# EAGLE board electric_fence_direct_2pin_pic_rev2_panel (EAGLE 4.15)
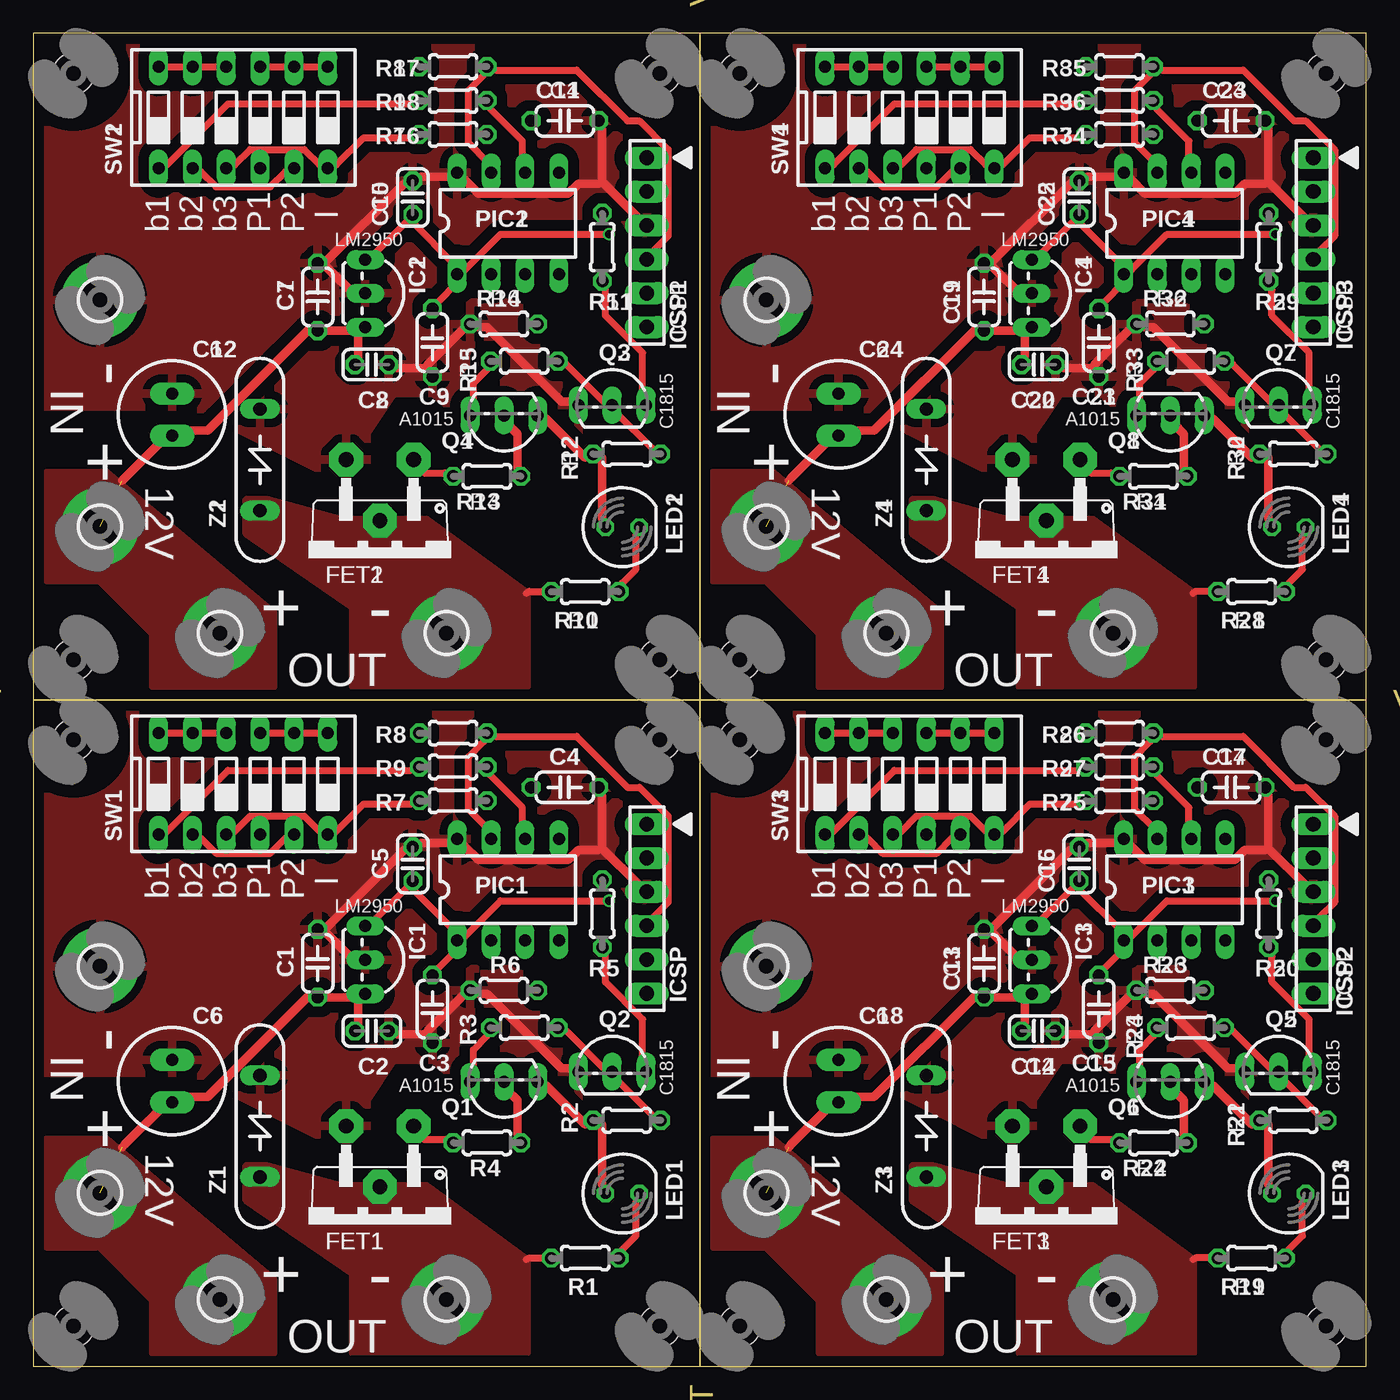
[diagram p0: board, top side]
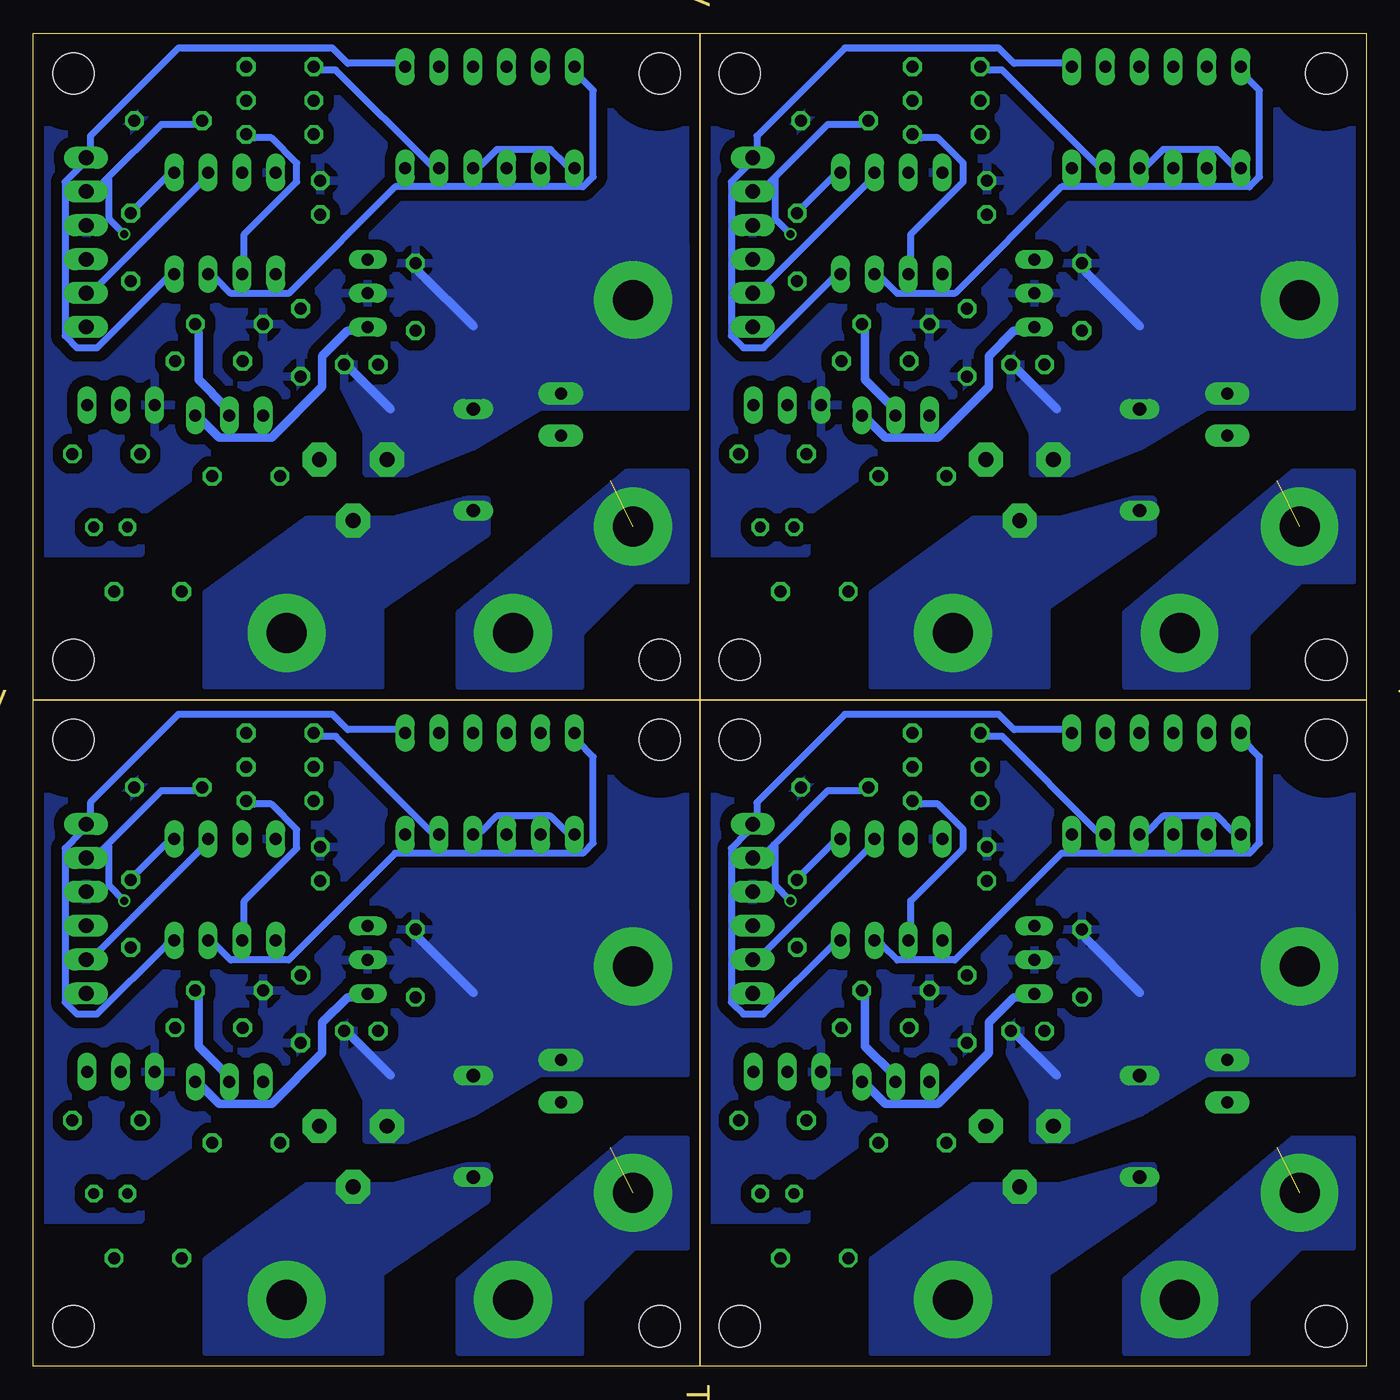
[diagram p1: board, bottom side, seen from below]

Size 100 x 100 mm. Coordinates in mm from the lower left corner, seen from the top.
Outline: 50,0 0,0 0,50
Outline: 50,0 50,50
Outline: 50,50 0,50
Outline: 0,50 50,50
Outline: 50,50 50,100
Outline: 50,100 0,100 0,50
Outline: 50,0 100,0 100,50
Outline: 100,50 50,50
Outline: 50,50 50,0
Outline: 50,50 100,50
Outline: 100,50 100,100 50,100
Outline: 50,100 50,50
Copper layers (1*16): Top 0.035mm / dielectric 1.5mm / Bottom 0.035mm
Design rules "FUSION_IIZUKA_STANDARD": minimum track width 6mil, minimum drill 0.6mm, track to track 8mil, track to pad 8mil, pad to pad 8mil, via to via 8mil, smd to smd 0mil, copper to edge 30mil, drill to drill 10mil, minimum pad ring 10mil, minimum via ring 6mil, stop-mask expansion 2mil, vias tented up to drill 100mil, thermal gap 24mil
Net classes: 0 default: width 0.508 mm, drill 0.406 mm; 1 power: width 0.635 mm, drill 0.508 mm

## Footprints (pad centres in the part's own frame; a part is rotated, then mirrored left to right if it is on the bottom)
C050-024X044_OLMX = drill 0.9 octagon: 1 -2.54,0; 2 2.54,0
C025-024X044_OLMX = drill 0.9 octagon: 1 -1.27,0; 2 1.27,0
C = drill 0.9 pad 1.676 long: P$1 1.27,0; P$2 -1.905,0
TO-220HV = drill 1.118 pad 2.54 octagon: 1 -2.54,-1.016; 2 0,3.556; 3 2.54,-1.016
3,0-PAD-NOLING = drill 3 pad 5.842 round: B3,0 0,0
3.1-HOLL = hole 3.1: 0,0
TO-92INLINE = drill 0.9 long: 1 -2.54,0; 2 0,0; 3 2.54,0
PIC_ICSP = drill 1.1 long: MCLR -6.35,0; NC 6.35,0; PGC 3.81,0; PGD 1.27,0; VDD -3.81,0; VSS -1.27,0
LED5MM_OLMX = drill 0.8 octagon: A -1.27,0; K 1.27,0
DIL8_OLMX = drill 0.9 long: 1 -3.81,-3.81; 2 -1.27,-3.81; 3 1.27,-3.81; 4 3.81,-3.81; 5 3.81,3.81; 6 1.27,3.81; 7 -1.27,3.81; 8 -3.81,3.81
TO92-BCE_OLMX = drill 0.9 long: B 2.54,0; C 0,0; E -2.54,0
0204/5_OLMX = drill 0.9 octagon: 1 -2.54,0; 2 2.54,0
DS-06_OLMX = drill 0.9 long: 1 -6.35,-3.81; 2 -3.81,-3.81; 3 -1.27,-3.81; 4 1.27,-3.81; 5 3.81,-3.81; 6 6.35,-3.81; 7 6.35,3.81; 8 3.81,3.81; 9 1.27,3.81; 10 -1.27,3.81; 11 -3.81,3.81; 12 -6.35,3.81
ZNR14MM = drill 1 long: P$1 -3.81,0; P$2 3.81,0

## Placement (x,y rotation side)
C1  10uF  [C050-024X044_OLMX]  21.34,30.23 270 top
C2  0.1uF  [C025-024X044_OLMX]  25.4,25.15 180 top
C3  10uF  [C050-024X044_OLMX]  29.94,26.8 90 top
C4  10uF  [C050-024X044_OLMX]  39.88,43.43 180 top
C5  0.1uF  [C025-024X044_OLMX]  28.47,37.68 270 top
C6  35V 220uF  [C]  10.41,21.08 270 top
C7  10uF  [C050-024X044_OLMX]  21.34,80.23 270 top
C8  0.1uF  [C025-024X044_OLMX]  25.4,75.15 180 top
C9  10uF  [C050-024X044_OLMX]  29.94,76.8 90 top
C10  0.1uF  [C025-024X044_OLMX]  28.47,87.68 270 top
C11  10uF  [C050-024X044_OLMX]  39.88,93.43 180 top
C12  35V 220uF  [C]  10.41,71.08 270 top
C13  10uF  [C050-024X044_OLMX]  71.34,30.23 270 top
C14  0.1uF  [C025-024X044_OLMX]  75.4,25.15 180 top
C15  10uF  [C050-024X044_OLMX]  79.94,26.8 90 top
C16  0.1uF  [C025-024X044_OLMX]  78.47,37.68 270 top
C17  10uF  [C050-024X044_OLMX]  89.88,43.43 180 top
C18  35V 220uF  [C]  60.41,21.08 270 top
C19  10uF  [C050-024X044_OLMX]  71.34,80.23 270 top
C20  0.1uF  [C025-024X044_OLMX]  75.4,75.15 180 top
C21  10uF  [C050-024X044_OLMX]  79.94,76.8 90 top
C22  0.1uF  [C025-024X044_OLMX]  78.47,87.68 270 top
C23  10uF  [C050-024X044_OLMX]  89.88,93.43 180 top
C24  35V 220uF  [C]  60.41,71.08 270 top
FET1  FQPF12N60C  [TO-220HV]  26,17 180 top
FET2  FQPF12N60C  [TO-220HV]  26,67 180 top
FET3  FQPF12N60C  [TO-220HV]  76,17 180 top
FET4  FQPF12N60C  [TO-220HV]  76,67 180 top
H1  [3,0-PAD-NOLING]  5,13 0 top
H2  [3,0-PAD-NOLING]  14,5 0 top
H3  [3,0-PAD-NOLING]  31,5 0 top
H4  [3,0-PAD-NOLING]  5,30 0 top
H5  MOUNT-HOLE3.1  [3.1-HOLL]  3,47 0 top
H6  MOUNT-HOLE3.1  [3.1-HOLL]  47,47 0 top
H7  MOUNT-HOLE3.1  [3.1-HOLL]  3,3 0 top
H8  MOUNT-HOLE3.1  [3.1-HOLL]  47,3 0 top
H9  [3,0-PAD-NOLING]  5,63 0 top
H10  [3,0-PAD-NOLING]  31,55 0 top
H11  [3,0-PAD-NOLING]  14,55 0 top
H12  [3,0-PAD-NOLING]  5,80 0 top
H13  MOUNT-HOLE3.1  [3.1-HOLL]  3,97 0 top
H14  MOUNT-HOLE3.1  [3.1-HOLL]  47,97 0 top
H15  MOUNT-HOLE3.1  [3.1-HOLL]  3,53 0 top
H16  MOUNT-HOLE3.1  [3.1-HOLL]  47,53 0 top
H17  [3,0-PAD-NOLING]  55,13 0 top
H18  [3,0-PAD-NOLING]  81,5 0 top
H19  [3,0-PAD-NOLING]  64,5 0 top
H20  [3,0-PAD-NOLING]  55,30 0 top
H21  MOUNT-HOLE3.1  [3.1-HOLL]  53,47 0 top
H22  MOUNT-HOLE3.1  [3.1-HOLL]  97,47 0 top
H23  MOUNT-HOLE3.1  [3.1-HOLL]  53,3 0 top
H24  MOUNT-HOLE3.1  [3.1-HOLL]  97,3 0 top
H25  [3,0-PAD-NOLING]  55,63 0 top
H26  [3,0-PAD-NOLING]  81,55 0 top
H27  [3,0-PAD-NOLING]  64,55 0 top
H28  [3,0-PAD-NOLING]  55,80 0 top
H29  MOUNT-HOLE3.1  [3.1-HOLL]  53,97 0 top
H30  MOUNT-HOLE3.1  [3.1-HOLL]  97,97 0 top
H31  MOUNT-HOLE3.1  [3.1-HOLL]  53,53 0 top
H32  MOUNT-HOLE3.1  [3.1-HOLL]  97,53 0 top
IC1  LM2950G-5.0  [TO-92INLINE]  24.91,30.49 270 top
IC2  LM2950G-5.0  [TO-92INLINE]  24.91,80.49 270 top
IC3  LM2950G-5.0  [TO-92INLINE]  74.91,30.49 270 top
IC4  LM2950G-5.0  [TO-92INLINE]  74.91,80.49 270 top
ICSP  PIC_ICSP  [PIC_ICSP]  46.03,34.32 270 top
ICSP1  PIC_ICSP  [PIC_ICSP]  46.03,84.32 270 top
ICSP2  PIC_ICSP  [PIC_ICSP]  96.03,34.32 270 top
ICSP3  PIC_ICSP  [PIC_ICSP]  96.03,84.32 270 top
LED1  [LED5MM_OLMX]  44.2,12.95 0 top
LED2  [LED5MM_OLMX]  44.2,62.95 0 top
LED3  [LED5MM_OLMX]  94.2,12.95 0 top
LED4  [LED5MM_OLMX]  94.2,62.95 0 top
PIC1  PIC12F1822  [DIL8_OLMX]  35.62,35.75 0 top
PIC2  PIC12F1822  [DIL8_OLMX]  35.62,85.75 0 top
PIC3  PIC12F1822  [DIL8_OLMX]  85.62,35.75 0 top
PIC4  PIC12F1822  [DIL8_OLMX]  85.62,85.75 0 top
Q1  2SA1015  [TO92-BCE_OLMX]  35.31,21.34 180 top
Q2  2SC1815-Y  [TO92-BCE_OLMX]  43.43,22.1 0 top
Q3  2SC1815-Y  [TO92-BCE_OLMX]  43.43,72.1 0 top
Q4  2SA1015  [TO92-BCE_OLMX]  35.31,71.34 180 top
Q5  2SC1815-Y  [TO92-BCE_OLMX]  93.43,22.1 0 top
Q6  2SA1015  [TO92-BCE_OLMX]  85.31,21.34 180 top
Q7  2SC1815-Y  [TO92-BCE_OLMX]  93.43,72.1 0 top
Q8  2SA1015  [TO92-BCE_OLMX]  85.31,71.34 180 top
R1  10k  [0204/5_OLMX]  41.4,8.11 180 top
R2  10k  [0204/5_OLMX]  44.53,18.45 180 top
R3  10k  [0204/5_OLMX]  36.83,25.4 180 top
R4  100  [0204/5_OLMX]  34.04,16.76 180 top
R5  10k  [0204/5_OLMX]  42.69,33.96 270 top
R6  1k  [0204/5_OLMX]  35.31,28.19 0 top
R7  1k  [0204/5_OLMX]  31.5,42.42 0 top
R8  1k  [0204/5_OLMX]  31.5,47.5 0 top
R9  1k  [0204/5_OLMX]  31.5,44.96 0 top
R10  10k  [0204/5_OLMX]  41.4,58.11 180 top
R11  10k  [0204/5_OLMX]  42.69,83.96 270 top
R12  10k  [0204/5_OLMX]  44.53,68.45 180 top
R13  100  [0204/5_OLMX]  34.04,66.76 180 top
R14  1k  [0204/5_OLMX]  35.31,78.19 0 top
R15  10k  [0204/5_OLMX]  36.83,75.4 180 top
R16  1k  [0204/5_OLMX]  31.5,92.42 0 top
R17  1k  [0204/5_OLMX]  31.5,97.5 0 top
R18  1k  [0204/5_OLMX]  31.5,94.96 0 top
R19  10k  [0204/5_OLMX]  91.4,8.11 180 top
R20  10k  [0204/5_OLMX]  92.69,33.96 270 top
R21  10k  [0204/5_OLMX]  94.53,18.45 180 top
R22  100  [0204/5_OLMX]  84.04,16.76 180 top
R23  1k  [0204/5_OLMX]  85.31,28.19 0 top
R24  10k  [0204/5_OLMX]  86.83,25.4 180 top
R25  1k  [0204/5_OLMX]  81.5,42.42 0 top
R26  1k  [0204/5_OLMX]  81.5,47.5 0 top
R27  1k  [0204/5_OLMX]  81.5,44.96 0 top
R28  10k  [0204/5_OLMX]  91.4,58.11 180 top
R29  10k  [0204/5_OLMX]  92.69,83.96 270 top
R30  10k  [0204/5_OLMX]  94.53,68.45 180 top
R31  100  [0204/5_OLMX]  84.04,66.76 180 top
R32  1k  [0204/5_OLMX]  85.31,78.19 0 top
R33  10k  [0204/5_OLMX]  86.83,75.4 180 top
R34  1k  [0204/5_OLMX]  81.5,92.42 0 top
R35  1k  [0204/5_OLMX]  81.5,97.5 0 top
R36  1k  [0204/5_OLMX]  81.5,94.96 0 top
SW1  [DS-06_OLMX]  15.75,43.69 0 top
SW2  [DS-06_OLMX]  15.75,93.69 0 top
SW3  [DS-06_OLMX]  65.75,43.69 0 top
SW4  [DS-06_OLMX]  65.75,93.69 0 top
Z1  14D471K  [ZNR14MM]  17,18 90 top
Z2  14D471K  [ZNR14MM]  17,68 90 top
Z3  14D471K  [ZNR14MM]  67,18 90 top
Z4  14D471K  [ZNR14MM]  67,68 90 top

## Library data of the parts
C1-C5 C7-C11 C13-C17 C19-C23 R1-R36 = rcl
C6 C12 C18 C24 = 002mylib
FET1-FET4 = transistor-power
H1-H32 = holes
IC1-IC4 = linear
ICSP ICSP1-ICSP3 Z1-Z4 = 001mylib
LED1-LED4 = led
PIC1-PIC4 = microchip
Q1-Q8 = transistor
SW1-SW4 = switch-dil

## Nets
+5V: C3.2 C4.2 C5.2 IC1.1 ICSP.VDD PIC1.1
+5V1: C9.2 C10.2 C11.2 IC2.1 ICSP1.VDD PIC2.1
+5V2: C15.2 C16.2 C17.2 IC3.1 ICSP2.VDD PIC3.1
+5V3: C21.2 C22.2 C23.2 IC4.1 ICSP3.VDD PIC4.1
GND [power]: C1.1 C2.1 C3.1 C4.1 C5.1 C6.P$2 FET1.3 H4.B3,0 IC1.2 ICSP.VSS PIC1.8 Q2.E R6.1 Z1.P$2
GND1 [power]: C7.1 C8.1 C9.1 C10.1 C11.1 C12.P$2 FET2.3 H12.B3,0 IC2.2 ICSP1.VSS PIC2.8 Q3.E R14.1 Z2.P$2
GND2 [power]: C13.1 C14.1 C15.1 C16.1 C17.1 C18.P$2 FET3.3 H20.B3,0 IC3.2 ICSP2.VSS PIC3.8 Q5.E R23.1 Z3.P$2
GND3 [power]: C19.1 C20.1 C21.1 C22.1 C23.1 C24.P$2 FET4.3 H28.B3,0 IC4.2 ICSP3.VSS PIC4.8 Q7.E R32.1 Z4.P$2
N$1: PIC1.2 R7.2
N$2: Q2.B R5.2
N$3: FET1.1 R4.2
N$4: R8.1 SW1.2 SW1.5
N$5: LED2.K R10.1
N$6 [power]: Q1.C R4.1 R6.2
N$7: LED1.K R1.1
N$8: Q1.B R3.2
N$9: ICSP.MCLR PIC1.4 SW1.7 SW1.8 SW1.9
N$10: R9.1 SW1.1 SW1.4
N$11: R7.1 SW1.3 SW1.6
N$12: Q2.C R2.1 R3.1
N$13: ICSP.PGD PIC1.7 R8.2
N$14: PIC1.3 SW1.10 SW1.11 SW1.12
N$15: PIC1.5 R5.1
N$16: ICSP.PGC PIC1.6 R9.2
N$17: PIC2.5 R11.1
N$18: Q3.B R11.2
N$19: FET2.1 R13.2
N$20: ICSP1.MCLR PIC2.4 SW2.7 SW2.8 SW2.9
N$21: R18.1 SW2.1 SW2.4
N$22: R17.1 SW2.2 SW2.5
N$23: R16.1 SW2.3 SW2.6
N$24: Q3.C R12.1 R15.1
N$25 [power]: Q4.C R13.1 R14.2
N$26: Q4.B R15.2
N$27: PIC2.3 SW2.10 SW2.11 SW2.12
N$28: PIC2.2 R16.2
N$29: ICSP1.PGD PIC2.7 R17.2
N$30: ICSP1.PGC PIC2.6 R18.2
N$31: LED3.K R19.1
N$32: PIC3.5 R20.1
N$33: Q5.B R20.2
N$34: FET3.1 R22.2
N$35: ICSP2.MCLR PIC3.4 SW3.7 SW3.8 SW3.9
N$36: R27.1 SW3.1 SW3.4
N$37: R26.1 SW3.2 SW3.5
N$38: R25.1 SW3.3 SW3.6
N$39: Q5.C R21.1 R24.1
N$40 [power]: Q6.C R22.1 R23.2
N$41: Q6.B R24.2
N$42: PIC3.3 SW3.10 SW3.11 SW3.12
N$43: PIC3.2 R25.2
N$44: ICSP2.PGD PIC3.7 R26.2
N$45: ICSP2.PGC PIC3.6 R27.2
N$46: LED4.K R28.1
N$47: PIC4.5 R29.1
N$48: Q7.B R29.2
N$49: FET4.1 R31.2
N$50: ICSP3.MCLR PIC4.4 SW4.7 SW4.8 SW4.9
N$51: R36.1 SW4.1 SW4.4
N$52: R35.1 SW4.2 SW4.5
N$53: R34.1 SW4.3 SW4.6
N$54: Q7.C R30.1 R33.1
N$55 [power]: Q8.C R31.1 R32.2
N$56: Q8.B R33.2
N$57: PIC4.3 SW4.10 SW4.11 SW4.12
N$58: PIC4.2 R34.2
N$59: ICSP3.PGD PIC4.7 R35.2
N$60: ICSP3.PGC PIC4.6 R36.2
OUT-: FET1.2 H3.B3,0 R1.2 Z1.P$1
OUT-1: FET2.2 H10.B3,0 R10.2 Z2.P$1
OUT-2: FET3.2 H18.B3,0 R19.2 Z3.P$1
OUT-3: FET4.2 H26.B3,0 R28.2 Z4.P$1
VPP [power]: C1.2 C2.2 C6.P$1 H1.B3,0 H2.B3,0 IC1.3 LED1.A Q1.E R2.2
VPP1 [power]: C7.2 C8.2 C12.P$1 H9.B3,0 H11.B3,0 IC2.3 LED2.A Q4.E R12.2
VPP2 [power]: C13.2 C14.2 C18.P$1 H17.B3,0 H19.B3,0 IC3.3 LED3.A Q6.E R21.2
VPP3 [power]: C19.2 C20.2 C24.P$1 H25.B3,0 H27.B3,0 IC4.3 LED4.A Q8.E R30.2

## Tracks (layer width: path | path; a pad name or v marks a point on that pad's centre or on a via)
+5V  (via drill 0.6)
  Top 0.508: C3.2 30.35,29.84 31.75,31.24 PIC1.1 | IC1.1 25.53,33.4 28.07,35.94 C5.2 28.45,35.81 31.62,32.64 PIC1.1 | v43.18,34.92 35.05,34.92 32.38,32.26 PIC1.1
  Bottom 0.508: 44.45,39.12 45.21,38.35 ICSP.VDD | 44.45,39.12 40.39,43.18 37.97,43.18 C4.2 | v43.18,34.92 44.32,36.07 44.32,38.99 44.45,39.12
+5V1  (via drill 0.6)
  Top 0.508: C9.2 30.35,79.84 31.75,81.24 PIC2.1 | IC2.1 25.53,83.4 28.07,85.94 C10.2 28.45,85.81 31.62,82.64 PIC2.1 | v43.18,84.92 35.05,84.92 32.38,82.26 PIC2.1
  Bottom 0.508: 44.45,89.12 45.21,88.35 ICSP1.VDD | 44.45,89.12 40.39,93.18 37.97,93.18 C11.2 | v43.18,84.92 44.32,86.07 44.32,88.99 44.45,89.12
+5V2  (via drill 0.6)
  Top 0.508: C15.2 80.35,29.84 81.75,31.24 PIC3.1 | IC3.1 75.53,33.4 78.07,35.94 C16.2 78.45,35.81 81.62,32.64 PIC3.1 | v93.18,34.92 85.05,34.92 82.39,32.26 PIC3.1
  Bottom 0.508: 94.45,39.12 95.21,38.35 ICSP2.VDD | 94.45,39.12 90.39,43.18 87.97,43.18 C17.2 | v93.18,34.92 94.32,36.07 94.32,38.99 94.45,39.12
+5V3  (via drill 0.6)
  Top 0.508: C21.2 80.35,79.84 81.75,81.24 PIC4.1 | IC4.1 75.53,83.4 78.07,85.94 C22.2 78.45,85.81 81.62,82.64 PIC4.1 | v93.18,84.92 85.05,84.92 82.39,82.26 PIC4.1
  Bottom 0.508: 94.45,89.12 95.21,88.35 ICSP3.VDD | 94.45,89.12 90.39,93.18 87.97,93.18 C23.2 | v93.18,84.92 94.32,86.07 94.32,88.99 94.45,89.12
GND
  Top 0.635: 29.59,24.89 27.3,24.89 C2.1 | 29.59,24.89 C3.1 | 29.59,24.89 29.59,25.15 32.26,27.81 R6.1 33.4,27.94 34.04,27.94 39.62,22.35 40.26,22.35 Q2.E | 42.67,38.86 42.67,42.8 C4.1 | 42.67,38.86 45.47,36.07 ICSP.VSS | IC1.2 24.26,30.23 21.97,32.51 C1.1 21.97,32.89 27.81,38.73 C5.1 29.08,39.24 31.24,39.24 PIC1.8 32.26,39.12 33.4,37.97 40.13,37.97 40.89,38.73 42.42,38.73 42.67,38.86
  Bottom 0.635: C2.1 26.16,24.77 23.2,21.8 | 16.98,28.02 21.08,32.13 C1.1
  pour Bottom (isolate 0.61, no thermals): 1,34.03 11,34 25,20 25,17 22,17 17,19 12,22 1,22
  pour Bottom (isolate 0.813, rank 2): 0,50 50,50 50,11 42,11 42,14 28,24 27,24 25,20 11,34 0,34
  pour Top (isolate 0.813, rank 2): 0,50 50,50 50,11 42,11 42,13 30,23 27,23 25,20 25,17 22,17 12,22 0,22
GND1
  Top 0.635: 29.59,74.89 27.3,74.89 C8.1 | 29.59,74.89 C9.1 | 29.59,74.89 29.59,75.15 32.26,77.81 R14.1 33.4,77.94 34.04,77.94 39.62,72.35 40.26,72.35 Q3.E | 42.67,88.86 42.67,92.8 C11.1 | 42.67,88.86 45.47,86.07 ICSP1.VSS | IC2.2 24.26,80.23 21.97,82.51 C7.1 21.97,82.89 27.81,88.73 C10.1 29.08,89.24 31.24,89.24 PIC2.8 32.26,89.12 33.4,87.97 40.13,87.97 40.89,88.73 42.42,88.73 42.67,88.86
  Bottom 0.635: C8.1 26.16,74.77 23.2,71.8 | 16.98,78.03 21.08,82.13 C7.1
  pour Bottom (isolate 0.61, no thermals): 1,84.03 11,84 25,70 25,67 22,67 17,69 12,72 1,72
  pour Bottom (isolate 0.813, rank 2): 0,100 50,100 50,61 42,61 42,64 28,74 27,74 25,70 11,84 0,84
  pour Top (isolate 0.813, rank 2): 0,100 50,100 50,61 42,61 42,63 30,73 27,73 25,70 25,67 22,67 12,72 0,72
GND2
  Top 0.635: 79.59,24.89 77.31,24.89 C14.1 | 79.59,24.89 C15.1 | 79.59,24.89 79.59,25.15 82.26,27.81 R23.1 83.4,27.94 84.04,27.94 89.62,22.35 90.26,22.35 Q5.E | 92.67,38.86 92.67,42.8 C17.1 | 92.67,38.86 95.47,36.07 ICSP2.VSS | IC3.2 74.26,30.23 71.97,32.51 C13.1 71.97,32.89 77.81,38.73 C16.1 79.08,39.24 81.24,39.24 PIC3.8 82.26,39.12 83.4,37.97 90.13,37.97 90.89,38.73 92.42,38.73 92.67,38.86
  Bottom 0.635: C14.1 76.16,24.77 73.2,21.8 | 66.97,28.02 71.08,32.13 C13.1
  pour Bottom (isolate 0.61, no thermals): 51,34.03 61,34 75,20 75,17 72,17 67,19 62,22 51,22
  pour Bottom (isolate 0.813, rank 2): 50,50 100,50 100,11 92,11 92,14 78,24 77,24 75,20 61,34 50,34
  pour Top (isolate 0.813, rank 2): 50,50 100,50 100,11 92,11 92,13 80,23 77,23 75,20 75,17 72,17 62,22 50,22
GND3
  Top 0.635: 79.59,74.89 77.31,74.89 C20.1 | 79.59,74.89 C21.1 | 79.59,74.89 79.59,75.15 82.26,77.81 R32.1 83.4,77.94 84.04,77.94 89.62,72.35 90.26,72.35 Q7.E | 92.67,88.86 92.67,92.8 C23.1 | 92.67,88.86 95.47,86.07 ICSP3.VSS | IC4.2 74.26,80.23 71.97,82.51 C19.1 71.97,82.89 77.81,88.73 C22.1 79.08,89.24 81.24,89.24 PIC4.8 82.26,89.12 83.4,87.97 90.13,87.97 90.89,88.73 92.42,88.73 92.67,88.86
  Bottom 0.635: C20.1 76.16,74.77 73.2,71.8 | 66.97,78.03 71.08,82.13 C19.1
  pour Bottom (isolate 0.61, no thermals): 51,84.03 61,84 75,70 75,67 72,67 67,69 62,72 51,72
  pour Bottom (isolate 0.813, rank 2): 50,100 100,100 100,61 92,61 92,64 78,74 77,74 75,70 61,84 50,84
  pour Top (isolate 0.813, rank 2): 50,100 100,100 100,61 92,61 92,63 80,73 77,73 75,70 75,67 72,67 62,72 50,72
N$1
  Bottom 0.508: PIC1.2 34.16,32.64 34.16,34.92 30.23,38.86 30.23,40.26 32.13,42.16 33.4,42.16 R7.2
N$2
  Top 0.508: Q2.B 45.72,22.73 45.72,26.04 42.93,28.83 42.93,30.73 R5.2
N$3
  Top 0.508: R4.2 30.86,17.02 29.34,17.02 FET1.1
N$4
  Top 0.508: SW1.2 12.57,39.62 13.72,38.48 17.78,38.48 18.92,39.62 SW1.5
  Bottom 0.508: R8.1 28.32,47.24 27.3,47.24 20.19,40.13 SW1.5
N$5
  Top 0.508: LED2.K 45.21,62.32 45.21,59.78 44.2,58.76 R10.1
N$6
  Top 0.635: R4.1 36.32,17.4 36.32,19.94 35.56,20.7 Q1.C
  Bottom 0.635: R6.2 37.59,27.56 37.59,24 35.56,21.97 Q1.C
N$7
  Top 0.508: LED1.K 45.21,12.32 45.21,9.78 44.2,8.76 R1.1
N$8
  Top 0.508: Q1.B 33.02,21.97 33.02,23.75 34.04,24.77 R3.2
N$9
  Top 0.508: SW1.9 SW1.8 SW1.7
  Bottom 0.508: PIC1.4 40.01,31.62 45.21,26.42 46.74,26.42 47.62,27.3 47.62,38.86 46.48,40.01 ICSP.MCLR 45.72,41.4 45.72,42.29 39.12,48.9 27.56,48.9 26.42,47.75 22.73,47.75 SW1.7
N$10
  Top 0.508: R9.1 28.32,44.7 14.61,44.7 10.03,40.13 SW1.1
  Bottom 0.508: SW1.1 10.03,40.13 11.18,41.27 15.24,41.27 16.38,40.13 SW1.4
N$11
  Top 0.508: SW1.3 15.11,40.13 16.26,41.27 20.32,41.27 21.46,40.13 SW1.6 22.73,40.13 24.77,42.16 28.32,42.16 R7.1
N$12
  Top 0.508: R3.1 40.01,25.15 42.8,22.35 Q2.C 43.69,21.59 46.48,18.8 R2.1
N$13
  Top 0.508: PIC1.7 34.16,40.26 32.64,41.78 32.64,45.72 33.78,46.86 R8.2 34.67,47.24 40.77,47.24 44.58,43.43 45.47,43.43 47.62,41.27 47.62,34.8 46.48,33.66 ICSP.PGD
N$14
  Top 0.508: SW1.12 SW1.11 SW1.10
  Bottom 0.508: PIC1.3 36.32,31.62 35.18,30.48 30.86,30.48 22.86,38.48 8.76,38.48 8,39.24 8,45.72 9.14,46.86 SW1.12
N$15
  Bottom 0.508: PIC1.5 40.01,39.24 42.29,36.96 R5.1
N$16
  Top 0.508: PIC1.6 36.7,40.26 36.7,41.91 34.29,44.32 R9.2
  Bottom 0.508: ICSP.PGC 45.34,30.86 37.21,38.99 PIC1.6
N$17
  Bottom 0.508: PIC2.5 40.01,89.24 42.29,86.96 R11.1
N$18
  Top 0.508: Q3.B 45.72,72.73 45.72,76.03 42.93,78.83 42.93,80.73 R11.2
N$19
  Top 0.508: R13.2 30.86,67.02 29.34,67.02 FET2.1
N$20
  Top 0.508: SW2.9 SW2.8 SW2.7
  Bottom 0.508: PIC2.4 40.01,81.62 45.21,76.42 46.74,76.42 47.62,77.31 47.62,88.86 46.48,90 ICSP1.MCLR 45.72,91.4 45.72,92.29 39.12,98.89 27.56,98.89 26.42,97.75 22.73,97.75 SW2.7
N$21
  Top 0.508: R18.1 28.32,94.7 14.61,94.7 10.03,90.13 SW2.1
  Bottom 0.508: SW2.1 10.03,90.13 11.18,91.28 15.24,91.28 16.38,90.13 SW2.4
N$22
  Top 0.508: SW2.2 12.57,89.62 13.72,88.48 17.78,88.48 18.92,89.62 SW2.5
  Bottom 0.508: R17.1 28.32,97.24 27.3,97.24 20.19,90.13 SW2.5
N$23
  Top 0.508: SW2.3 15.11,90.13 16.26,91.28 20.32,91.28 21.46,90.13 SW2.6 22.73,90.13 24.77,92.16 28.32,92.16 R16.1
N$24
  Top 0.508: R15.1 40.01,75.15 42.8,72.35 Q3.C 43.69,71.59 46.48,68.8 R12.1
N$25
  Top 0.635: R13.1 36.32,67.4 36.32,69.94 35.56,70.7 Q4.C
  Bottom 0.635: R14.2 37.59,77.56 37.59,74 35.56,71.97 Q4.C
N$26
  Top 0.508: Q4.B 33.02,71.97 33.02,73.75 34.04,74.77 R15.2
N$27
  Top 0.508: SW2.12 SW2.11 SW2.10
  Bottom 0.508: PIC2.3 36.32,81.62 35.18,80.48 30.86,80.48 22.86,88.48 8.76,88.48 8,89.24 8,95.72 9.14,96.86 SW2.12
N$28
  Bottom 0.508: PIC2.2 34.16,82.64 34.16,84.92 30.23,88.86 30.23,90.26 32.13,92.16 33.4,92.16 R16.2
N$29
  Top 0.508: PIC2.7 34.16,90.26 32.64,91.78 32.64,95.72 33.78,96.86 R17.2 34.67,97.24 40.77,97.24 44.58,93.43 45.47,93.43 47.62,91.28 47.62,84.8 46.48,83.66 ICSP1.PGD
N$30
  Top 0.508: PIC2.6 36.7,90.26 36.7,91.91 34.29,94.32 R18.2
  Bottom 0.508: ICSP1.PGC 45.34,80.86 37.21,88.99 PIC2.6
N$31
  Top 0.508: LED3.K 95.21,12.32 95.21,9.78 94.2,8.76 R19.1
N$32
  Bottom 0.508: PIC3.5 90,39.24 92.29,36.96 R20.1
N$33
  Top 0.508: Q5.B 95.72,22.73 95.72,26.04 92.93,28.83 92.93,30.73 R20.2
N$34
  Top 0.508: R22.2 80.86,17.02 79.34,17.02 FET3.1
N$35
  Top 0.508: SW3.9 SW3.8 SW3.7
  Bottom 0.508: PIC3.4 90,31.62 95.21,26.42 96.74,26.42 97.62,27.3 97.62,38.86 96.48,40.01 ICSP2.MCLR 95.72,41.4 95.72,42.29 89.12,48.9 77.56,48.9 76.42,47.75 72.73,47.75 SW3.7
N$36
  Top 0.508: R27.1 78.32,44.7 64.61,44.7 60.03,40.13 SW3.1
  Bottom 0.508: SW3.1 60.03,40.13 61.18,41.27 65.24,41.27 66.38,40.13 SW3.4
N$37
  Top 0.508: SW3.2 62.57,39.62 63.72,38.48 67.78,38.48 68.92,39.62 SW3.5
  Bottom 0.508: R26.1 78.32,47.24 77.31,47.24 70.19,40.13 SW3.5
N$38
  Top 0.508: SW3.3 65.11,40.13 66.26,41.27 70.32,41.27 71.46,40.13 SW3.6 72.73,40.13 74.77,42.16 78.32,42.16 R25.1
N$39
  Top 0.508: R24.1 90,25.15 92.8,22.35 Q5.C 93.69,21.59 96.48,18.8 R21.1
N$40
  Top 0.635: R22.1 86.32,17.4 86.32,19.94 85.56,20.7 Q6.C
  Bottom 0.635: R23.2 87.59,27.56 87.59,24 85.56,21.97 Q6.C
N$41
  Top 0.508: Q6.B 83.02,21.97 83.02,23.75 84.04,24.77 R24.2
N$42
  Top 0.508: SW3.12 SW3.11 SW3.10
  Bottom 0.508: PIC3.3 86.32,31.62 85.18,30.48 80.86,30.48 72.86,38.48 58.76,38.48 58,39.24 58,45.72 59.14,46.86 SW3.12
N$43
  Bottom 0.508: PIC3.2 84.16,32.64 84.16,34.92 80.23,38.86 80.23,40.26 82.13,42.16 83.4,42.16 R25.2
N$44
  Top 0.508: PIC3.7 84.16,40.26 82.64,41.78 82.64,45.72 83.78,46.86 R26.2 84.67,47.24 90.77,47.24 94.58,43.43 95.47,43.43 97.62,41.27 97.62,34.8 96.48,33.66 ICSP2.PGD
N$45
  Top 0.508: PIC3.6 86.7,40.26 86.7,41.91 84.29,44.32 R27.2
  Bottom 0.508: ICSP2.PGC 95.34,30.86 87.21,38.99 PIC3.6
N$46
  Top 0.508: LED4.K 95.21,62.32 95.21,59.78 94.2,58.76 R28.1
N$47
  Bottom 0.508: PIC4.5 90,89.24 92.29,86.96 R29.1
N$48
  Top 0.508: Q7.B 95.72,72.73 95.72,76.03 92.93,78.83 92.93,80.73 R29.2
N$49
  Top 0.508: R31.2 80.86,67.02 79.34,67.02 FET4.1
N$50
  Top 0.508: SW4.9 SW4.8 SW4.7
  Bottom 0.508: PIC4.4 90,81.62 95.21,76.42 96.74,76.42 97.62,77.31 97.62,88.86 96.48,90 ICSP3.MCLR 95.72,91.4 95.72,92.29 89.12,98.89 77.56,98.89 76.42,97.75 72.73,97.75 SW4.7
N$51
  Top 0.508: R36.1 78.32,94.7 64.61,94.7 60.03,90.13 SW4.1
  Bottom 0.508: SW4.1 60.03,90.13 61.18,91.28 65.24,91.28 66.38,90.13 SW4.4
N$52
  Top 0.508: SW4.2 62.57,89.62 63.72,88.48 67.78,88.48 68.92,89.62 SW4.5
  Bottom 0.508: R35.1 78.32,97.24 77.31,97.24 70.19,90.13 SW4.5
N$53
  Top 0.508: SW4.3 65.11,90.13 66.26,91.28 70.32,91.28 71.46,90.13 SW4.6 72.73,90.13 74.77,92.16 78.32,92.16 R34.1
N$54
  Top 0.508: R33.1 90,75.15 92.8,72.35 Q7.C 93.69,71.59 96.48,68.8 R30.1
N$55
  Top 0.635: R31.1 86.32,67.4 86.32,69.94 85.56,70.7 Q8.C
  Bottom 0.635: R32.2 87.59,77.56 87.59,74 85.56,71.97 Q8.C
N$56
  Top 0.508: Q8.B 83.02,71.97 83.02,73.75 84.04,74.77 R33.2
N$57
  Top 0.508: SW4.12 SW4.11 SW4.10
  Bottom 0.508: PIC4.3 86.32,81.62 85.18,80.48 80.86,80.48 72.86,88.48 58.76,88.48 58,89.24 58,95.72 59.14,96.86 SW4.12
N$58
  Bottom 0.508: PIC4.2 84.16,82.64 84.16,84.92 80.23,88.86 80.23,90.26 82.13,92.16 83.4,92.16 R34.2
N$59
  Top 0.508: PIC4.7 84.16,90.26 82.64,91.78 82.64,95.72 83.78,96.86 R35.2 84.67,97.24 90.77,97.24 94.58,93.43 95.47,93.43 97.62,91.28 97.62,84.8 96.48,83.66 ICSP3.PGD
N$60
  Top 0.508: PIC4.6 86.7,90.26 86.7,91.91 84.29,94.32 R36.2
  Bottom 0.508: ICSP3.PGC 95.34,80.86 87.21,88.99 PIC4.6
OUT-
  Top 0.508: R1.2 38.23,8.13 37.21,8.13 37,8
  pour Bottom (isolate 0.813, no thermals): 23,13.5 17.5,15 16,15 16,12.5 24,7 24,1 37,1 37,8 29.5,13.5
  pour Top (isolate 0.813, no thermals): 16,15 16,12.5 24,7 24,1 37,1 37,8 29.5,13.5 23,13.5 17.5,15
OUT-1
  Top 0.508: R10.2 38.23,58.13 37.21,58.13 37,58
  pour Bottom (isolate 0.813, no thermals): 23,63.5 17.5,65 16,65 16,62.5 24,57 24,51 37,51 37,58 29.5,63.5
  pour Top (isolate 0.813, no thermals): 16,65 16,62.5 24,57 24,51 37,51 37,58 29.5,63.5 23,63.5 17.5,65
OUT-2
  Top 0.508: R19.2 88.23,8.13 87.21,8.13 87,8
  pour Bottom (isolate 0.813, no thermals): 73,13.5 67.5,15 66,15 66,12.5 74,7 74,1 87,1 87,8 79.5,13.5
  pour Top (isolate 0.813, no thermals): 66,15 66,12.5 74,7 74,1 87,1 87,8 79.5,13.5 73,13.5 67.5,15
OUT-3
  Top 0.508: R28.2 88.23,58.13 87.21,58.13 87,58
  pour Bottom (isolate 0.813, no thermals): 73,63.5 67.5,65 66,65 66,62.5 74,57 74,51 87,51 87,58 79.5,63.5
  pour Top (isolate 0.813, no thermals): 66,65 66,62.5 74,57 74,51 87,51 87,58 79.5,63.5 73,63.5 67.5,65
VPP  (1 unrouted)
  Top 0.635: LED1.A 42.67,13.59 42.67,18.16 R2.2 41.4,18.16 38.48,21.08 Q1.E | 6.68,16.43 6.86,16.64 9.65,19.43 C6.P$1 11.18,20.19 13.08,20.19 20.7,27.81 C1.2 24.13,27.69 24.38,27.56 | 24.38,27.56 24.38,25.78 C2.2 | 24.38,27.56 IC1.3
  Bottom 0.635: Q1.E 37.34,20.95 36.07,19.68 32.13,19.68 28.32,23.5 28.32,25.78 26.42,27.69 25.53,27.69 IC1.3
  pour Bottom (isolate 0.61, no thermals): 1,17 1,9 5,9 9,5 9,1 12,1 11,1 18,1 18,6.5 5.5,17
  pour Top (no thermals): 1,17 5.5,17 18,6.5 18,1 9,1 9,5 5,9 1,9
VPP1  (1 unrouted)
  Top 0.635: LED2.A 42.67,63.59 42.67,68.16 R12.2 41.4,68.16 38.48,71.08 Q4.E | 6.68,66.43 6.86,66.64 9.65,69.43 C12.P$1 11.18,70.19 13.08,70.19 20.7,77.81 C7.2 24.13,77.69 24.38,77.56 | 24.38,77.56 24.38,75.78 C8.2 | 24.38,77.56 IC2.3
  Bottom 0.635: Q4.E 37.34,70.95 36.07,69.69 32.13,69.69 28.32,73.5 28.32,75.78 26.42,77.69 25.53,77.69 IC2.3
  pour Bottom (isolate 0.61, no thermals): 1,67 1,59 5,59 9,55 9,51 12,51 11,51 18,51 18,56.5 5.5,67
  pour Top (no thermals): 1,67 5.5,67 18,56.5 18,51 9,51 9,55 5,59 1,59
VPP2  (1 unrouted)
  Top 0.635: LED3.A 92.67,13.59 92.67,18.16 R21.2 91.4,18.16 88.48,21.08 Q6.E | 56.69,16.43 56.86,16.64 59.65,19.43 C18.P$1 61.18,20.19 63.08,20.19 70.7,27.81 C13.2 74.13,27.69 74.38,27.56 | 74.38,27.56 74.38,25.78 C14.2 | 74.38,27.56 IC3.3
  Bottom 0.635: Q6.E 87.34,20.95 86.07,19.68 82.13,19.68 78.32,23.5 78.32,25.78 76.42,27.69 75.53,27.69 IC3.3
  pour Bottom (isolate 0.61, no thermals): 51,17 51,9 55,9 59,5 59,1 62,1 61,1 68,1 68,6.5 55.5,17
  pour Top (no thermals): 51,17 55.5,17 68,6.5 68,1 59,1 59,5 55,9 51,9
VPP3  (1 unrouted)
  Top 0.635: LED4.A 92.67,63.59 92.67,68.16 R30.2 91.4,68.16 88.48,71.08 Q8.E | 56.69,66.43 56.86,66.64 59.65,69.43 C24.P$1 61.18,70.19 63.08,70.19 70.7,77.81 C19.2 74.13,77.69 74.38,77.56 | 74.38,77.56 74.38,75.78 C20.2 | 74.38,77.56 IC4.3
  Bottom 0.635: Q8.E 87.34,70.95 86.07,69.69 82.13,69.69 78.32,73.5 78.32,75.78 76.42,77.69 75.53,77.69 IC4.3
  pour Bottom (isolate 0.61, no thermals): 51,67 51,59 55,59 59,55 59,51 62,51 61,51 68,51 68,56.5 55.5,67
  pour Top (no thermals): 51,67 55.5,67 68,56.5 68,51 59,51 59,55 55,59 51,59

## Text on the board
Dimension: V-CUT | V-CUT | V-CUT | V-CUT
tPlace: I | I | b1 | b2 | b3 | P1 | P2 | b1 | b2 | b3 | P1 | P2 | LM2950 | LM2950 | - | - | IN | IN | A1015 | A1015 | C1815 | C1815 | + | 12V | + | 12V | + | - | + | - | OUT | OUT | I | I | b1 | b2 | b3 | P1 | P2 | b1 | b2 | b3 | P1 | P2 | LM2950 | LM2950 | - | - | IN | IN | A1015 | A1015 | C1815 | C1815 | + | 12V | + | 12V | + | - | + | - | OUT | OUT
_tNames: R8 | R8 | C4 | C4 | R9 | R9 | R7 | R7 | SW1 | C5 | SW1 | C5 | PIC1 | PIC1 | C1 | R6 | ICSP | C1 | R6 | ICSP | IC1 | IC1 | R5 | R5 | C6 | R3 | C6 | R3 | Q2 | Q2 | C2 | C3 | C2 | C3 | Q1 | R2 | Q1 | R2 | R4 | R4 | Z1 | Z1 | LED1 | LED1 | FET1 | FET1 | R1 | R1 | R8 | R8 | C4 | C4 | R9 | R9 | R7 | R7 | SW1 | C5 | SW1 | C5 | PIC1 | PIC1 | C1 | R6 | ICSP | C1 | R6 | ICSP | IC1 | IC1 | R5 | R5 | C6 | R3 | C6 | R3 | Q2 | Q2 | C2 | C3 | C2 | C3 | Q1 | R2 | Q1 | R2 | R4 | R4 | Z1 | Z1 | LED1 | LED1 | FET1 | FET1 | R1 | R1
